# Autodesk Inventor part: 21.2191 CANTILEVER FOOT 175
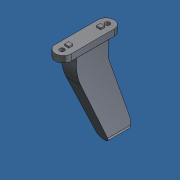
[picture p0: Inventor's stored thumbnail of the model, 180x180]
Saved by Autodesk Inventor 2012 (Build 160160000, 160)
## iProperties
Created: 2014-05
Part Number: 21.2191 CANTILEVER FOOT 175
Material: Aluminum-6061
Document SubType Name: Modeling
Designer: Admin
Density: 2.71 g/cm^3
Mass: 731.611 g
Surface Area: 370.84 cm^2
Volume: 269.967 cm^3
Author: Admin
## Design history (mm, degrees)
node "31"
sketch "Sketch1"
  geometry: C1 r 4.188 at (0, 0) reference; 2 further points
  constraints: 1 coincident
hole "Hole1" sketch "Sketch1" at (0, 0) diameter "d0" = 8.382; stored, may be unused: countersink angle "d4" = 82 deg, drill point angle "d6" = 118 deg; dims "d1" = 25, "d2" = 9.525, "d3" = 6.35, "d5" = 28
node "Base1"
body "Solid1"
